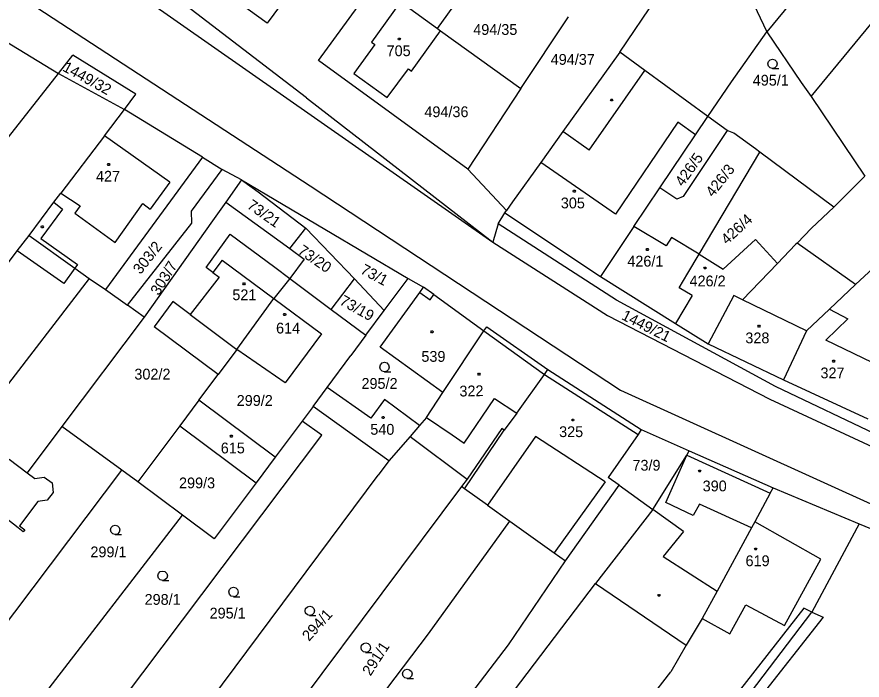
# Model space of a CAD drawing. Extents: x -580630 to -576196, y -1189024 to -1183567.
# Drawn here: x -579205 to -579071.8, y -1185628.9 to -1185524.4 of the extents above; entities that cross this region are included whole.
import ezdxf

# ---------------------------------------------------------------- set-up
doc = ezdxf.new("R2010")
doc.units = 0
for name, color, linetype in [('Vrstva 1', 7, 'Continuous'), ('Vrstva 18', 7, 'Continuous'), ('Vrstva 19', 7, 'Continuous'), ('Vrstva 25', 7, 'Continuous'), ('Vrstva 4', 7, 'Continuous'), ('Vrstva 6', 7, 'Continuous')]:
    doc.layers.add(name, color=color, linetype=linetype)

msp = doc.modelspace()

# ---------------------------------------------------------------- linework, layer by layer
at = {"layer": 'Vrstva 1'}
for p, q in [((-579062.68, -1185497.15), (-579086.75, -1185526.81)), ((-579159.35, -1185537.21), (-579201.77, -1185504.64)), ((-579165.55, -1185525.45), (-579195.71, -1185503.52)), ((-579079.8, -1185537.01), (-579053.65, -1185505.24)), ((-579109.95, -1185530.02), (-579095.39, -1185508.35)), ((-579156.24, -1185512.61), (-579165.55, -1185525.45)), ((-579093.22, -1185513.26), (-579086.75, -1185526.81)), ((-579157.46, -1185531.33), (-579148.62, -1185519.13)), ((-579144.53, -1185522.07), (-579149.11, -1185528.4)), ((-579138.72, -1185526.26), (-579135.42, -1185521.7)), ((-579144, -1185522.46), (-579138.72, -1185526.26)), ((-579125.56, -1185535.74), (-579118.04, -1185524.44)), ((-579142.78, -1185533.01), (-579138.21, -1185526.63)), ((-579138.72, -1185526.26), (-579138.21, -1185526.63)), ((-579138.21, -1185526.63), (-579125.56, -1185535.74)), ((-579092.34, -1185534.65), (-579086.75, -1185526.81)), ((-579086.75, -1185526.81), (-579081.36, -1185534.78)), ((-579208.08, -1185527.55), (-579198.46, -1185533.34)), ((-579148.58, -1185528.78), (-579151.89, -1185533.36)), ((-579149.11, -1185528.4), (-579148.58, -1185528.78)), ((-579109.95, -1185530.02), (-579118.92, -1185542.5)), ((-579105.99, -1185532.91), (-579109.95, -1185530.02)), ((-579133.93, -1185548.43), (-579157.46, -1185531.33)), ((-579146.63, -1185537.15), (-579143.29, -1185532.64)), ((-579143.29, -1185532.64), (-579142.78, -1185533.01)), ((-579251.17, -1185600.43), (-579198.46, -1185533.34)), ((-579198.46, -1185533.34), (-579188.07, -1185539.01)), ((-579151.89, -1185533.36), (-579146.63, -1185537.15)), ((-579096.06, -1185540.14), (-579105.99, -1185532.91)), ((-579096.06, -1185540.14), (-579092.34, -1185534.65)), ((-579081.36, -1185534.78), (-579079.8, -1185537.01)), ((-579125.56, -1185535.74), (-579133.93, -1185548.43)), ((-579159.35, -1185537.21), (-579129.97, -1185559.92)), ((-579079.8, -1185537.01), (-579071.31, -1185549.53)), ((-579191.22, -1185543.16), (-579188.07, -1185539.01)), ((-579175.78, -1185546.55), (-579188.07, -1185539.01)), ((-579098.02, -1185543.05), (-579096.06, -1185540.14)), ((-579093.04, -1185542.36), (-579096.06, -1185540.14)), ((-579191.22, -1185543.16), (-579198.08, -1185552.21)), ((-579118.92, -1185542.5), (-579122.42, -1185547.37)), ((-579103.65, -1185551.37), (-579098.02, -1185543.05)), ((-579093.04, -1185542.36), (-579099.95, -1185552.74)), ((-579092, -1185542.74), (-579093.04, -1185542.36)), ((-579088.58, -1185545.23), (-579092, -1185542.74)), ((-579097.44, -1185561.83), (-579087.88, -1185545.76)), ((-579087.88, -1185545.76), (-579088.58, -1185545.23)), ((-579076.22, -1185554.41), (-579087.88, -1185545.76)), ((-579175.78, -1185546.55), (-579191.07, -1185567.39)), ((-579175.78, -1185546.55), (-579172.66, -1185548.48)), ((-579122.42, -1185547.37), (-579126.87, -1185553.56)), ((-579177.49, -1185555.03), (-579172.66, -1185548.48)), ((-579169.62, -1185550.12), (-579172.66, -1185548.48)), ((-579133.93, -1185548.43), (-579127.84, -1185554.97)), ((-579071.31, -1185549.53), (-579076.22, -1185554.41)), ((-579169.62, -1185550.12), (-579172.09, -1185553.61)), ((-579169.62, -1185550.12), (-579143.35, -1185565.66)), ((-579169.62, -1185550.12), (-579166.96, -1185552.03)), ((-579107.75, -1185557.49), (-579103.65, -1185551.37)), ((-579100.97, -1185553.14), (-579103.65, -1185551.37)), ((-579199.2, -1185553.62), (-579198.08, -1185552.21)), ((-579099.95, -1185552.74), (-579100.97, -1185553.14)), ((-579203.11, -1185558.86), (-579199.2, -1185553.62)), ((-579172.09, -1185553.61), (-579174.18, -1185556.57)), ((-579172.09, -1185553.61), (-579162, -1185560.93)), ((-579126.87, -1185553.56), (-579127.84, -1185554.97)), ((-579177.43, -1185556.92), (-579177.49, -1185555.03)), ((-579129.11, -1185557.03), (-579128.09, -1185555.29)), ((-579128.09, -1185555.29), (-579127.84, -1185554.97)), ((-579128.09, -1185555.29), (-579113.02, -1185565.34)), ((-579076.22, -1185554.41), (-579079.75, -1185557.74)), ((-579174.18, -1185556.57), (-579184.96, -1185571.78)), ((-579187.59, -1185569.87), (-579177.43, -1185556.92)), ((-579162, -1185560.93), (-579159.44, -1185557.74)), ((-579129.11, -1185557.03), (-579129.97, -1185559.92)), ((-579110.48, -1185569.05), (-579129.11, -1185557.03)), ((-579107.75, -1185557.49), (-579113.02, -1185565.34)), ((-579102.67, -1185560.5), (-579107.75, -1185557.49)), ((-579079.75, -1185557.74), (-579082, -1185560.07)), ((-579204.96, -1185561.31), (-579203.11, -1185558.86)), ((-579203.11, -1185558.86), (-579195.87, -1185564.02)), ((-579175.19, -1185563.91), (-579171.38, -1185558.66)), ((-579171.38, -1185558.66), (-579164.37, -1185563.88)), ((-579101.81, -1185559.18), (-579102.67, -1185560.5)), ((-579097.44, -1185561.83), (-579101.81, -1185559.18)), ((-579129.97, -1185559.92), (-579111.92, -1185571.47)), ((-579093.64, -1185564.17), (-579088.55, -1185559.51)), ((-579088.55, -1185559.51), (-579085.1, -1185563.29)), ((-579082.25, -1185560.33), (-579085.1, -1185563.29)), ((-579082, -1185560.07), (-579082.25, -1185560.33)), ((-579072.81, -1185566.62), (-579082, -1185560.07)), ((-579241.01, -1185608.56), (-579204.96, -1185561.31)), ((-579162, -1185560.93), (-579159.72, -1185562.59)), ((-579099.22, -1185564.83), (-579097.44, -1185561.83)), ((-579097.44, -1185561.83), (-579093.64, -1185564.17)), ((-579072.81, -1185566.62), (-579067.79, -1185561.94)), ((-579159.72, -1185562.59), (-579162.01, -1185565.64)), ((-579085.1, -1185563.29), (-579090.6, -1185569)), ((-579195.87, -1185564.02), (-579193.62, -1185565.67)), ((-579174.15, -1185564.69), (-579175.19, -1185563.91)), ((-579174.15, -1185564.69), (-579173.15, -1185565.44)), ((-579164.37, -1185563.88), (-579162.01, -1185565.64)), ((-579193.62, -1185565.67), (-579231.92, -1185615.35)), ((-579193.62, -1185565.67), (-579191.07, -1185567.39)), ((-579173.15, -1185565.44), (-579177.71, -1185571.33)), ((-579162.01, -1185565.64), (-579164.49, -1185568.81)), ((-579162.01, -1185565.64), (-579155.46, -1185570.53)), ((-579147.1, -1185570.68), (-579143.35, -1185565.66)), ((-579143.35, -1185565.66), (-579140.89, -1185567.05)), ((-579113.02, -1185565.34), (-579101.17, -1185572.74)), ((-579100.58, -1185567.11), (-579099.22, -1185564.83)), ((-579191.07, -1185567.39), (-579187.59, -1185569.87)), ((-579141.47, -1185567.86), (-579140.89, -1185567.05)), ((-579139.3, -1185568.2), (-579140.89, -1185567.05)), ((-579098.53, -1185568.32), (-579100.58, -1185567.11)), ((-579076.88, -1185570.47), (-579072.81, -1185566.62)), ((-579147.72, -1185576.49), (-579141.47, -1185567.86)), ((-579139.3, -1185568.2), (-579131.4, -1185573.92)), ((-579098.53, -1185568.32), (-579101.17, -1185572.74)), ((-579091.96, -1185568.34), (-579096.03, -1185575.95)), ((-579090.6, -1185569), (-579091.96, -1185568.34)), ((-579184.96, -1185571.78), (-579187.59, -1185569.87)), ((-579180.43, -1185569.29), (-579183.4, -1185573.26)), ((-579177.71, -1185571.33), (-579180.43, -1185569.29)), ((-579170.34, -1185576.84), (-579164.49, -1185568.81)), ((-579164.49, -1185568.81), (-579156.99, -1185574.38)), ((-579085.38, -1185582.68), (-579110.48, -1185569.05)), ((-579155.46, -1185570.53), (-579149.99, -1185574.61)), ((-579149.99, -1185574.61), (-579147.1, -1185570.68)), ((-579080.52, -1185573.9), (-579076.88, -1185570.47)), ((-579184.96, -1185571.78), (-579197.93, -1185588.99)), ((-579111.92, -1185571.47), (-579086.32, -1185584.7)), ((-579101.17, -1185572.74), (-579096.03, -1185575.95)), ((-579173.31, -1185580.8), (-579183.4, -1185573.26)), ((-579137.86, -1185583.65), (-579131.4, -1185573.92)), ((-579131.4, -1185573.92), (-579130.94, -1185573.27)), ((-579130.94, -1185573.27), (-579121.32, -1185580)), ((-579080.52, -1185573.9), (-579084.16, -1185581.61)), ((-579156.99, -1185574.38), (-579162.73, -1185582.08)), ((-579149.99, -1185574.61), (-579152.38, -1185577.82)), ((-579137.86, -1185583.65), (-579147.72, -1185576.49)), ((-579096.03, -1185575.95), (-579084.16, -1185581.61)), ((-579170.34, -1185576.84), (-579173.31, -1185580.8)), ((-579162.73, -1185582.08), (-579170.34, -1185576.84)), ((-579156.11, -1185582.85), (-579152.38, -1185577.82)), ((-579121.83, -1185580.79), (-579121.32, -1185580)), ((-579121.32, -1185580), (-579106.58, -1185589.46)), ((-579176.32, -1185584.82), (-579173.31, -1185580.8)), ((-579126.17, -1185586.88), (-579121.83, -1185580.79)), ((-579084.16, -1185581.61), (-579070.82, -1185587.76)), ((-579158.32, -1185585.82), (-579156.11, -1185582.85)), ((-579149.21, -1185587.67), (-579156.11, -1185582.85)), ((-579061.46, -1185594.1), (-579085.38, -1185582.68)), ((-579147.07, -1185584.75), (-579149.21, -1185587.67)), ((-579141.54, -1185588.83), (-579147.07, -1185584.75)), ((-579140.46, -1185587.57), (-579137.86, -1185583.65)), ((-579086.32, -1185584.7), (-579062.32, -1185595.79)), ((-579176.32, -1185584.82), (-579179.34, -1185588.87)), ((-579164.29, -1185593.79), (-579176.32, -1185584.82)), ((-579158.32, -1185585.82), (-579160.05, -1185588.13)), ((-579146.37, -1185594.38), (-579158.32, -1185585.82)), ((-579126.17, -1185586.88), (-579128.17, -1185589.57)), ((-579160.05, -1185588.13), (-579164.29, -1185593.79)), ((-579156.95, -1185590.34), (-579160.05, -1185588.13)), ((-579140.46, -1185587.57), (-579141.54, -1185588.83)), ((-579197.93, -1185588.99), (-579203.38, -1185596.26)), ((-579188.46, -1185595.86), (-579197.93, -1185588.99)), ((-579179.34, -1185588.87), (-579185.93, -1185597.7)), ((-579179.34, -1185588.87), (-579167.31, -1185597.85)), ((-579141.54, -1185588.83), (-579143.02, -1185590.58)), ((-579128.58, -1185589.27), (-579134.02, -1185597.27)), ((-579128.17, -1185589.57), (-579128.58, -1185589.27)), ((-579106.58, -1185589.46), (-579107.06, -1185590.25)), ((-579106.58, -1185589.46), (-579099.03, -1185592.83)), ((-579195.8, -1185641.86), (-579156.95, -1185590.34)), ((-579143.02, -1185590.58), (-579146.37, -1185594.38)), ((-579143.02, -1185590.58), (-579134.02, -1185597.27)), ((-579107.06, -1185590.25), (-579111.77, -1185597.01)), ((-579164.29, -1185593.79), (-579167.31, -1185597.85)), ((-579104.74, -1185602.08), (-579099.36, -1185593.5)), ((-579099.36, -1185593.5), (-579099.03, -1185592.83)), ((-579099.03, -1185592.83), (-579085.76, -1185598.63)), ((-579206.22, -1185594.11), (-579203.38, -1185596.26)), ((-579146.37, -1185594.38), (-579148.06, -1185596.67)), ((-579213.69, -1185629.23), (-579188.46, -1185595.86)), ((-579203.38, -1185596.26), (-579202.18, -1185597.17)), ((-579185.93, -1185597.7), (-579188.46, -1185595.86)), ((-579186.04, -1185647.53), (-579148.06, -1185596.67)), ((-579202.18, -1185597.17), (-579200.7, -1185596.96)), ((-579200.7, -1185596.96), (-579199.48, -1185597.87)), ((-579199.48, -1185597.87), (-579199.29, -1185599.36)), ((-579178.89, -1185602.96), (-579185.93, -1185597.7)), ((-579167.31, -1185597.85), (-579173.91, -1185606.67)), ((-579134.02, -1185597.27), (-579134.91, -1185598.45)), ((-579110.03, -1185598.25), (-579111.77, -1185597.01)), ((-579199.29, -1185599.36), (-579200.23, -1185600.6)), ((-579134.91, -1185598.45), (-579176.22, -1185653.63)), ((-579134.45, -1185598.78), (-579134.91, -1185598.45)), ((-579130.83, -1185601.37), (-579134.45, -1185598.78)), ((-579118.5, -1185610.15), (-579110.03, -1185598.25)), ((-579110.03, -1185598.25), (-579104.74, -1185602.08)), ((-579086.24, -1185599.49), (-579085.76, -1185598.63)), ((-579085.76, -1185598.63), (-579072.19, -1185604.32)), ((-579200.23, -1185600.6), (-579201.73, -1185600.8)), ((-579086.24, -1185599.49), (-579088.66, -1185604.01)), ((-579201.73, -1185600.8), (-579204.59, -1185604.63)), ((-579130.83, -1185601.37), (-579127.31, -1185603.88)), ((-579104.74, -1185602.08), (-579113.81, -1185613.73)), ((-579204.81, -1185604.94), (-579208.05, -1185602.49)), ((-579204.6, -1185636.23), (-579178.89, -1185602.96)), ((-579173.91, -1185606.67), (-579178.89, -1185602.96)), ((-579204.59, -1185604.63), (-579203.78, -1185605.26)), ((-579140.14, -1185621.66), (-579127.31, -1185603.88)), ((-579127.31, -1185603.88), (-579120.28, -1185608.88)), ((-579088.66, -1185604.01), (-579089.17, -1185604.95)), ((-579078.25, -1185609.91), (-579088.66, -1185604.01)), ((-579072.19, -1185604.32), (-579079.67, -1185618.21)), ((-579072.19, -1185604.32), (-579067.31, -1185606.37)), ((-579204.01, -1185605.56), (-579204.81, -1185604.94)), ((-579203.78, -1185605.26), (-579204.01, -1185605.56)), ((-579089.17, -1185604.95), (-579094.62, -1185614.92)), ((-579120.28, -1185608.88), (-579118.5, -1185610.15)), ((-579084, -1185620.35), (-579078.25, -1185609.91)), ((-579127.48, -1185623.39), (-579118.5, -1185610.15)), ((-579153.96, -1185666.53), (-579113.81, -1185613.73)), ((-579113.81, -1185613.73), (-579099.47, -1185623.46)), ((-579094.62, -1185614.92), (-579096.97, -1185619.21)), ((-579080.95, -1185617.59), (-579120.53, -1185668.18)), ((-579092.61, -1185621.63), (-579090.06, -1185617.08)), ((-579090.06, -1185617.08), (-579084, -1185620.35)), ((-579079.67, -1185618.21), (-579080.95, -1185617.59)), ((-579077.88, -1185619.02), (-579120.84, -1185673.48)), ((-579101, -1185646.24), (-579079.67, -1185618.21)), ((-579096.97, -1185619.21), (-579099.47, -1185623.46)), ((-579096.97, -1185619.21), (-579092.61, -1185621.63)), ((-579079.67, -1185618.21), (-579077.88, -1185619.02)), ((-579167.71, -1185658.11), (-579140.14, -1185621.66)), ((-579158.7, -1185663.98), (-579127.48, -1185623.39)), ((-579099.47, -1185623.46), (-579101.92, -1185627.64)), ((-579139.44, -1185676.04), (-579101.92, -1185627.64))]:
    msp.add_line(p, q, dxfattribs=at)
at = {"layer": 'Vrstva 25'}
for points in [[(-579144.65, -1185527.78), (-579144.56, -1185527.93), (-579144.65, -1185528.08), (-579144.83, -1185528.08), (-579144.92, -1185527.93), (-579144.83, -1185527.78)], [(-579111.14, -1185537.38), (-579111.05, -1185537.53), (-579111.14, -1185537.68), (-579111.32, -1185537.68), (-579111.41, -1185537.53), (-579111.32, -1185537.38)], [(-579190.47, -1185547.55), (-579190.38, -1185547.7), (-579190.47, -1185547.85), (-579190.65, -1185547.85), (-579190.74, -1185547.7), (-579190.65, -1185547.55)], [(-579117.05, -1185551.76), (-579116.96, -1185551.91), (-579117.05, -1185552.06), (-579117.23, -1185552.06), (-579117.32, -1185551.91), (-579117.23, -1185551.76)], [(-579200.94, -1185557.36), (-579200.85, -1185557.51), (-579200.94, -1185557.66), (-579201.12, -1185557.66), (-579201.21, -1185557.51), (-579201.12, -1185557.36)], [(-579105.52, -1185560.93), (-579105.43, -1185561.08), (-579105.52, -1185561.23), (-579105.7, -1185561.23), (-579105.79, -1185561.08), (-579105.7, -1185560.93)], [(-579096.41, -1185563.86), (-579096.32, -1185564.01), (-579096.41, -1185564.16), (-579096.59, -1185564.16), (-579096.68, -1185564.01), (-579096.59, -1185563.86)], [(-579169.11, -1185566.35), (-579169.02, -1185566.5), (-579169.11, -1185566.65), (-579169.29, -1185566.65), (-579169.38, -1185566.5), (-579169.29, -1185566.35)], [(-579162.69, -1185571.19), (-579162.6, -1185571.34), (-579162.69, -1185571.49), (-579162.87, -1185571.49), (-579162.96, -1185571.34), (-579162.87, -1185571.19)], [(-579139.46, -1185573.93), (-579139.37, -1185574.08), (-579139.46, -1185574.23), (-579139.64, -1185574.23), (-579139.73, -1185574.08), (-579139.64, -1185573.93)], [(-579087.93, -1185573.02), (-579087.84, -1185573.17), (-579087.93, -1185573.32), (-579088.11, -1185573.32), (-579088.2, -1185573.17), (-579088.11, -1185573.02)], [(-579076.15, -1185578.54), (-579076.06, -1185578.69), (-579076.15, -1185578.84), (-579076.33, -1185578.84), (-579076.42, -1185578.69), (-579076.33, -1185578.54)], [(-579132.07, -1185580.57), (-579131.98, -1185580.72), (-579132.07, -1185580.87), (-579132.25, -1185580.87), (-579132.34, -1185580.72), (-579132.25, -1185580.57)], [(-579147.18, -1185587.43), (-579147.09, -1185587.58), (-579147.18, -1185587.73), (-579147.36, -1185587.73), (-579147.45, -1185587.58), (-579147.36, -1185587.43)], [(-579117.27, -1185587.8), (-579117.18, -1185587.95), (-579117.27, -1185588.1), (-579117.45, -1185588.1), (-579117.54, -1185587.95), (-579117.45, -1185587.8)], [(-579171.13, -1185590.37), (-579171.04, -1185590.52), (-579171.13, -1185590.67), (-579171.31, -1185590.67), (-579171.4, -1185590.52), (-579171.31, -1185590.37)], [(-579097.28, -1185595.85), (-579097.19, -1185596), (-579097.28, -1185596.15), (-579097.46, -1185596.15), (-579097.55, -1185596), (-579097.46, -1185595.85)], [(-579088.43, -1185608.14), (-579088.34, -1185608.29), (-579088.43, -1185608.44), (-579088.61, -1185608.44), (-579088.7, -1185608.29), (-579088.61, -1185608.14)], [(-579103.67, -1185615.44), (-579103.58, -1185615.59), (-579103.67, -1185615.74), (-579103.85, -1185615.74), (-579103.94, -1185615.59), (-579103.85, -1185615.44)]]:
    msp.add_lwpolyline(points, close=True, dxfattribs=at)
for points in [[(-579085.86, -1185532.57), (-579086.24, -1185532.47), (-579086.51, -1185532.2), (-579086.61, -1185531.83), (-579086.51, -1185531.46), (-579086.24, -1185531.19), (-579085.87, -1185531.09), (-579085.5, -1185531.19), (-579085.23, -1185531.46), (-579085.13, -1185531.84), (-579085.23, -1185532.22), (-579085.5, -1185532.49), (-579085.88, -1185532.59), (-579084.88, -1185532.59)], [(-579147.06, -1185580.35), (-579147.44, -1185580.25), (-579147.71, -1185579.98), (-579147.81, -1185579.61), (-579147.71, -1185579.24), (-579147.44, -1185578.97), (-579147.07, -1185578.87), (-579146.7, -1185578.97), (-579146.43, -1185579.24), (-579146.33, -1185579.62), (-579146.43, -1185580), (-579146.7, -1185580.27), (-579147.08, -1185580.37), (-579146.08, -1185580.37)], [(-579189.53, -1185606), (-579189.91, -1185605.9), (-579190.18, -1185605.63), (-579190.28, -1185605.26), (-579190.18, -1185604.89), (-579189.91, -1185604.62), (-579189.54, -1185604.52), (-579189.17, -1185604.62), (-579188.9, -1185604.89), (-579188.8, -1185605.27), (-579188.9, -1185605.65), (-579189.17, -1185605.92), (-579189.55, -1185606.02), (-579188.55, -1185606.02)], [(-579182.03, -1185613.23), (-579182.41, -1185613.13), (-579182.68, -1185612.86), (-579182.78, -1185612.49), (-579182.68, -1185612.12), (-579182.41, -1185611.85), (-579182.04, -1185611.75), (-579181.67, -1185611.85), (-579181.4, -1185612.12), (-579181.3, -1185612.5), (-579181.4, -1185612.88), (-579181.67, -1185613.15), (-579182.05, -1185613.25), (-579181.05, -1185613.25)], [(-579170.87, -1185615.79), (-579171.25, -1185615.69), (-579171.52, -1185615.42), (-579171.62, -1185615.05), (-579171.52, -1185614.68), (-579171.25, -1185614.41), (-579170.88, -1185614.31), (-579170.51, -1185614.41), (-579170.24, -1185614.68), (-579170.14, -1185615.06), (-579170.24, -1185615.44), (-579170.51, -1185615.71), (-579170.89, -1185615.81), (-579169.89, -1185615.81)], [(-579158.84, -1185618.76), (-579159.22, -1185618.66), (-579159.49, -1185618.39), (-579159.59, -1185618.02), (-579159.49, -1185617.65), (-579159.22, -1185617.38), (-579158.85, -1185617.28), (-579158.48, -1185617.38), (-579158.21, -1185617.65), (-579158.11, -1185618.03), (-579158.21, -1185618.41), (-579158.48, -1185618.68), (-579158.86, -1185618.78), (-579157.86, -1185618.78)], [(-579150.01, -1185624.56), (-579150.39, -1185624.46), (-579150.66, -1185624.19), (-579150.76, -1185623.82), (-579150.66, -1185623.45), (-579150.39, -1185623.18), (-579150.02, -1185623.08), (-579149.65, -1185623.18), (-579149.38, -1185623.45), (-579149.28, -1185623.83), (-579149.38, -1185624.21), (-579149.65, -1185624.48), (-579150.03, -1185624.58), (-579149.03, -1185624.58)], [(-579143.45, -1185628.69), (-579143.83, -1185628.59), (-579144.1, -1185628.32), (-579144.2, -1185627.95), (-579144.1, -1185627.58), (-579143.83, -1185627.31), (-579143.46, -1185627.21), (-579143.09, -1185627.31), (-579142.82, -1185627.58), (-579142.72, -1185627.96), (-579142.82, -1185628.34), (-579143.09, -1185628.61), (-579143.47, -1185628.71), (-579142.47, -1185628.71)]]:
    msp.add_lwpolyline(points, dxfattribs=at)
at = {"layer": 'Vrstva 4'}
for p, q in [((-579199.27, -1185511.52), (-579129.97, -1185559.92)), ((-579212.23, -1185516.2), (-579158.8, -1185551.05)), ((-579114.8, -1185545.45), (-579105.99, -1185532.91)), ((-579100.8, -1185541.02), (-579110.62, -1185555.51)), ((-579098.02, -1185543.05), (-579100.8, -1185541.02)), ((-579180.92, -1185550.5), (-579191.22, -1185543.16)), ((-579114.8, -1185545.45), (-579118.92, -1185542.5)), ((-579110.62, -1185555.51), (-579122.42, -1185547.37)), ((-579180.92, -1185550.5), (-579184.03, -1185554.72)), ((-579158.8, -1185551.05), (-579109.86, -1185583.25)), ((-579198.08, -1185552.21), (-579195.07, -1185554.23)), ((-579199.2, -1185553.62), (-579197.81, -1185554.72)), ((-579189.54, -1185560), (-579185.18, -1185553.86)), ((-579185.18, -1185553.86), (-579184.03, -1185554.72)), ((-579197.81, -1185554.72), (-579201.26, -1185559.37)), ((-579195.07, -1185554.23), (-579195.87, -1185555.38)), ((-579195.87, -1185555.38), (-579189.54, -1185560)), ((-579201.26, -1185559.37), (-579195.46, -1185563.45)), ((-579197.62, -1185566.47), (-579204.96, -1185561.31)), ((-579172.68, -1185562.77), (-579174.15, -1185564.69)), ((-579172.68, -1185562.77), (-579164.49, -1185568.81)), ((-579195.87, -1185564.02), (-579197.62, -1185566.47)), ((-579195.46, -1185563.45), (-579195.87, -1185564.02)), ((-579141.47, -1185567.86), (-579139.88, -1185569.02)), ((-579139.88, -1185569.02), (-579139.3, -1185568.2)), ((-579080.52, -1185573.9), (-579090.6, -1185569)), ((-579177.71, -1185571.33), (-579170.34, -1185576.84)), ((-579076.88, -1185570.47), (-579074.02, -1185572.03)), ((-579077.46, -1185575.38), (-579074.02, -1185572.03)), ((-579131.4, -1185573.92), (-579121.83, -1185580.79)), ((-579067.47, -1185580.22), (-579077.46, -1185575.38)), ((-579121.83, -1185580.79), (-579107.06, -1185590.25)), ((-579109.86, -1185583.25), (-579009.27, -1185628.86)), ((-579134.49, -1185591.59), (-579129.7, -1185584.55)), ((-579129.7, -1185584.55), (-579126.17, -1185586.88)), ((-579140.46, -1185587.57), (-579136.39, -1185590.28)), ((-579134.45, -1185598.78), (-579128.17, -1185589.57)), ((-579136.39, -1185590.28), (-579134.49, -1185591.59)), ((-579123.24, -1185590.57), (-579130.83, -1185601.37)), ((-579112.26, -1185597.72), (-579123.24, -1185590.57)), ((-579102.71, -1185600.94), (-579099.36, -1185593.5)), ((-579099.36, -1185593.5), (-579086.24, -1185599.49)), ((-579112.26, -1185597.72), (-579120.28, -1185608.88)), ((-579099.93, -1185605.55), (-579104.74, -1185602.08)), ((-579098.4, -1185602.99), (-579102.71, -1185600.94)), ((-579097.4, -1185601.21), (-579098.4, -1185602.99)), ((-579089.17, -1185604.95), (-579097.4, -1185601.21)), ((-579099.93, -1185605.55), (-579103.13, -1185609.44)), ((-579103.13, -1185609.44), (-579094.62, -1185614.92))]:
    msp.add_line(p, q, dxfattribs=at)
at = {"layer": 'Vrstva 6'}
for p, q in [((-579198.46, -1185533.34), (-579196.22, -1185530.49)), ((-579186.27, -1185536.63), (-579196.22, -1185530.49)), ((-579188.07, -1185539.01), (-579186.27, -1185536.63)), ((-579166.96, -1185552.03), (-579159.44, -1185557.74)), ((-579159.44, -1185557.74), (-579151.81, -1185565.74)), ((-579155.46, -1185570.53), (-579151.81, -1185565.74)), ((-579151.81, -1185565.74), (-579147.1, -1185570.68))]:
    msp.add_line(p, q, dxfattribs=at)

# ---------------------------------------------------------------- texts
at = {"layer": 'Vrstva 18'}
for s, p in [('494/35', (-579133.066, -1185527.28)), ('494/37', (-579120.849, -1185531.99)), ('495/1', (-579088.992, -1185535.27)), ('494/36', (-579140.769, -1185540.24)), ('302/2', (-579186.494, -1185581.58)), ('295/2', (-579150.687, -1185583.05)), ('299/2', (-579170.36, -1185585.73)), ('73/9', (-579107.961, -1185595.94)), ('299/3', (-579179.454, -1185598.72)), ('299/1', (-579193.429, -1185609.59)), ('298/1', (-579184.886, -1185617.08)), ('295/1', (-579174.636, -1185619.24))]:
    msp.add_text(s, height=1.7, dxfattribs=at).set_placement(p)
for s, rotation, p in [('1449/32', 331.2269, (-579197.943, -1185532.864)), ('73/21', 325.03896, (-579168.867, -1185554.473)), ('303/2', 51.73809, (-579185.536, -1185565.121)), ('73/20', 325.26814, (-579160.863, -1185561.62)), ('303/7', 58.09792, (-579182.649, -1185568.451)), ('73/1', 331.62797, (-579150.999, -1185564.769)), ('73/19', 330.76854, (-579154.283, -1185569.661)), ('1449/21', 333.11766, (-579109.817, -1185572.026)), ('294/1', 47.89927, (-579158.958, -1185622.914)), ('291/1', 57.12389, (-579149.266, -1185628.391))]:
    msp.add_text(s, height=1.7, rotation=rotation, dxfattribs=at).set_placement(p)
at = {"layer": 'Vrstva 19'}
for s, p in [('705', (-579146.728, -1185530.63)), ('427', (-579192.548, -1185550.4)), ('305', (-579119.255, -1185554.61)), ('426/1', (-579108.769, -1185563.78)), ('426/2', (-579098.96, -1185566.9)), ('521', (-579171.047, -1185569.08)), ('614', (-579164.156, -1185574.33)), ('328', (-579090.155, -1185575.87)), ('539', (-579141.238, -1185578.79)), ('327', (-579078.315, -1185581.39)), ('540', (-579149.298, -1185590.28)), ('325', (-579119.522, -1185590.65)), ('615', (-579172.873, -1185593.22)), ('390', (-579096.888, -1185599.2)), ('619', (-579090.126, -1185610.99))]:
    msp.add_text(s, height=1.7, dxfattribs=at).set_placement(p)
for s, rotation, p in [('426/5', 54.77476, (-579100, -1185551.293)), ('426/3', 51.68079, (-579095.248, -1185552.95)), ('426/4', 42.62806, (-579093.05, -1185560.425)), ('322', 1.08862, (-579135.228, -1185584.262))]:
    msp.add_text(s, height=1.7, rotation=rotation, dxfattribs=at).set_placement(p)

doc.saveas('drawing.dxf')
